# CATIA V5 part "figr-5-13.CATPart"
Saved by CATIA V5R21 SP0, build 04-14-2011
Part number: Part1
Bounding box of the stored display mesh (mm): x 0 to 150, y -70 to 70, z -150 to 69.804
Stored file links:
  D:\CATIA V5R21 E-RESOURCES\CATIA-V5R21\catia-v5r21-prt\c05-catia-v5r20-prt\catia-v5r21-figr-5-13.CATPart
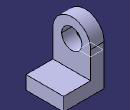
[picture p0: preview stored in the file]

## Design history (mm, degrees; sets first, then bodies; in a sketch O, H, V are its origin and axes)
Set1
  Plane1: type Normal, Curve edge [face of Pad1 | face of Pad1], RefPoint vertex of Pad2
Body1 (main body)
  Sketch1 on yz-plane, origin (0, 0, 0), H (0, 1, 0), V (0, 0, 1)
    arc A1 centre (0, 0) radius 70 from (70, 0) to (-70, 0) ccw
    point P1 (70, 0)
    point P2 (-70, 0)
    line L1 (-70, 0) -> (-70, -150)
    line L2 (-70, -150) -> (70, -150)
    line L3 (70, -150) -> (70, 0)
    circle A2 centre (0, 0) radius 37.5
    radius A1 = 70
    radius A2 = 37.5
    distance O L2 = 150
    coincidence: P1 H, P2 H
    tangency: L1 A1, L3 A1
    horizontal: L2 H
  Pad1: profile Sketch1, direction (1, 0, 0), length 50
  Sketch2 on face of Pad1, origin (50, 0, 0), H (0, 1, 0), V (0, 0, 1)
    line L1 (-70, -150) -> (70, -150)
    line L2 (70, -150) -> (70, -100)
    line L3 (70, -100) -> (-70, -100)
    line L4 (-70, -100) -> (-70, -150)
    reference projected line E1 (-70, -150) -> (70, -150) from edge [face of Pad1 | face of Pad1]
    reference projected line E2 (-70, 0) -> (-70, -150) from edge [face of Pad1 | face of Pad1]
    reference projected line E3 (70, -150) -> (70, 0) from edge [face of Pad1 | face of Pad1]
    length L2 = 50
    horizontal: L1 H, L3 H
    vertical: L2 V, L4 V
    coincidence: L1 E1, E2 L4, L2 E3
  Pad2: profile Sketch2, direction (1, 0, 0), length 100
